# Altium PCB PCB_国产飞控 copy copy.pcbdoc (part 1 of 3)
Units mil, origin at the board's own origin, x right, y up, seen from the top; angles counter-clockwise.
Board outline 2782.5 x 2450 mil, 4 copper layers (Top Layer, Inner1, Inner2, Bottom Layer), stack 2.757 mil thick; 92 components, 104 nets, 474 pads, 149 vias.
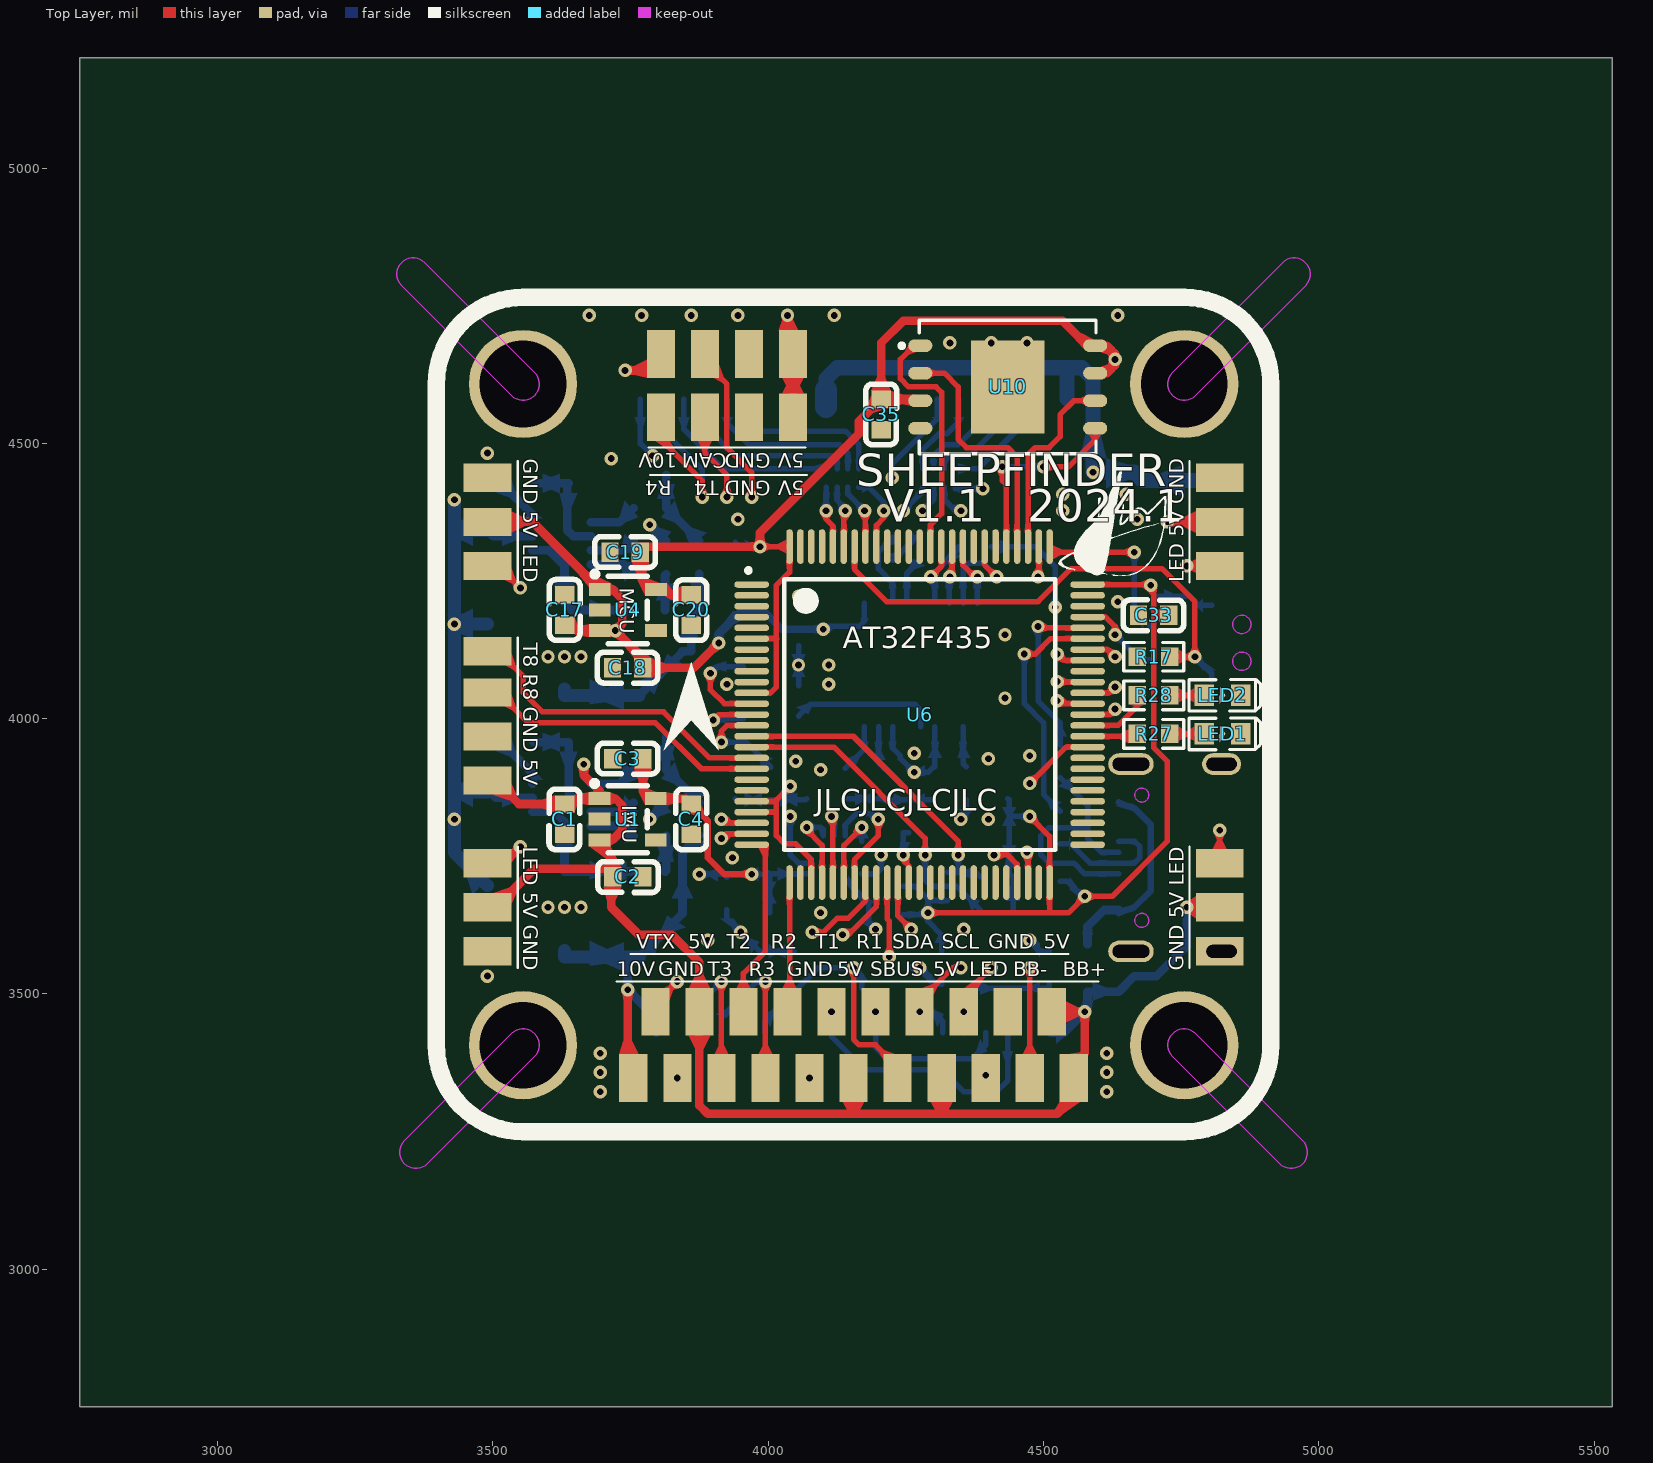
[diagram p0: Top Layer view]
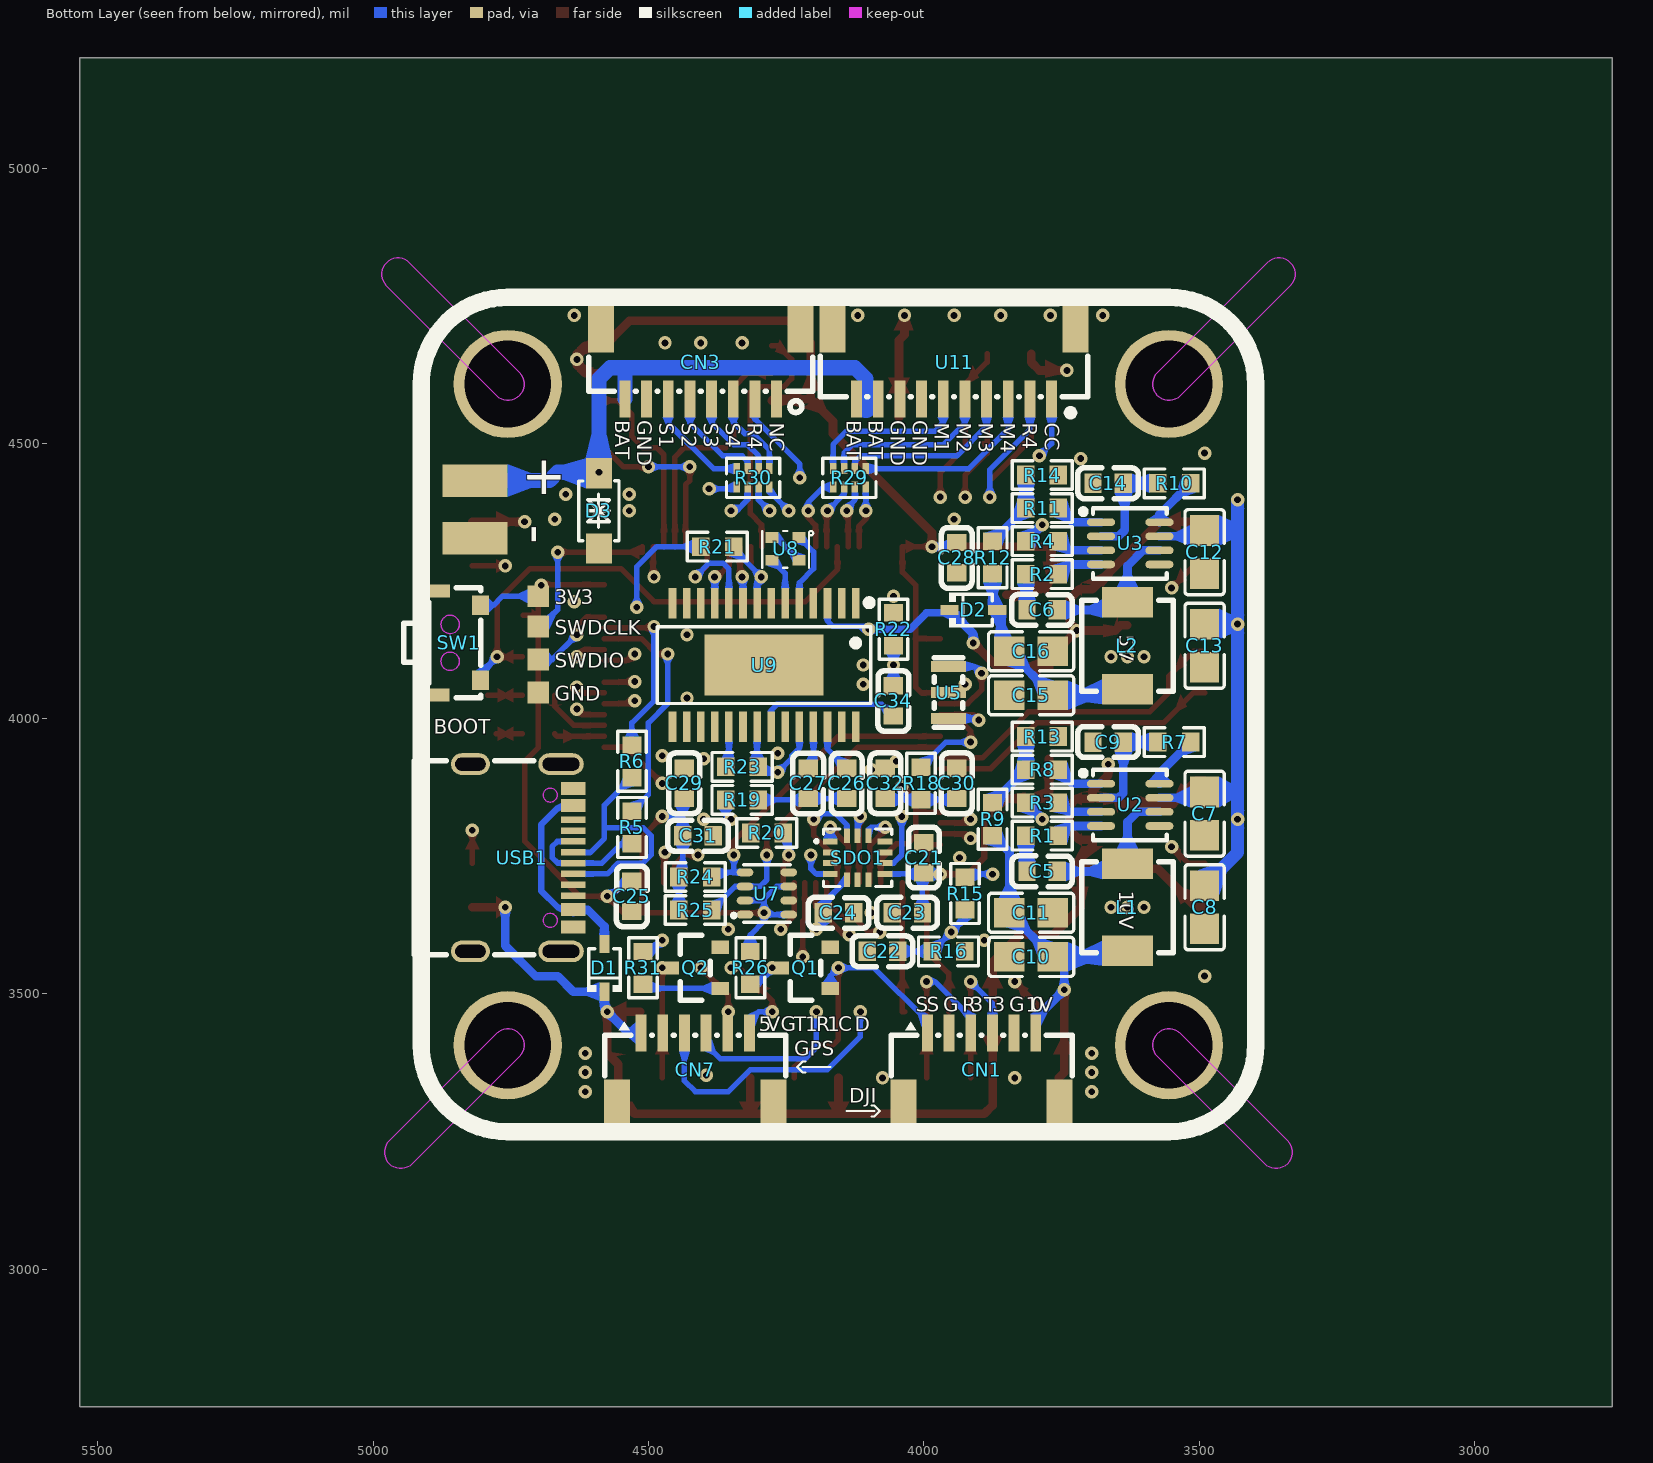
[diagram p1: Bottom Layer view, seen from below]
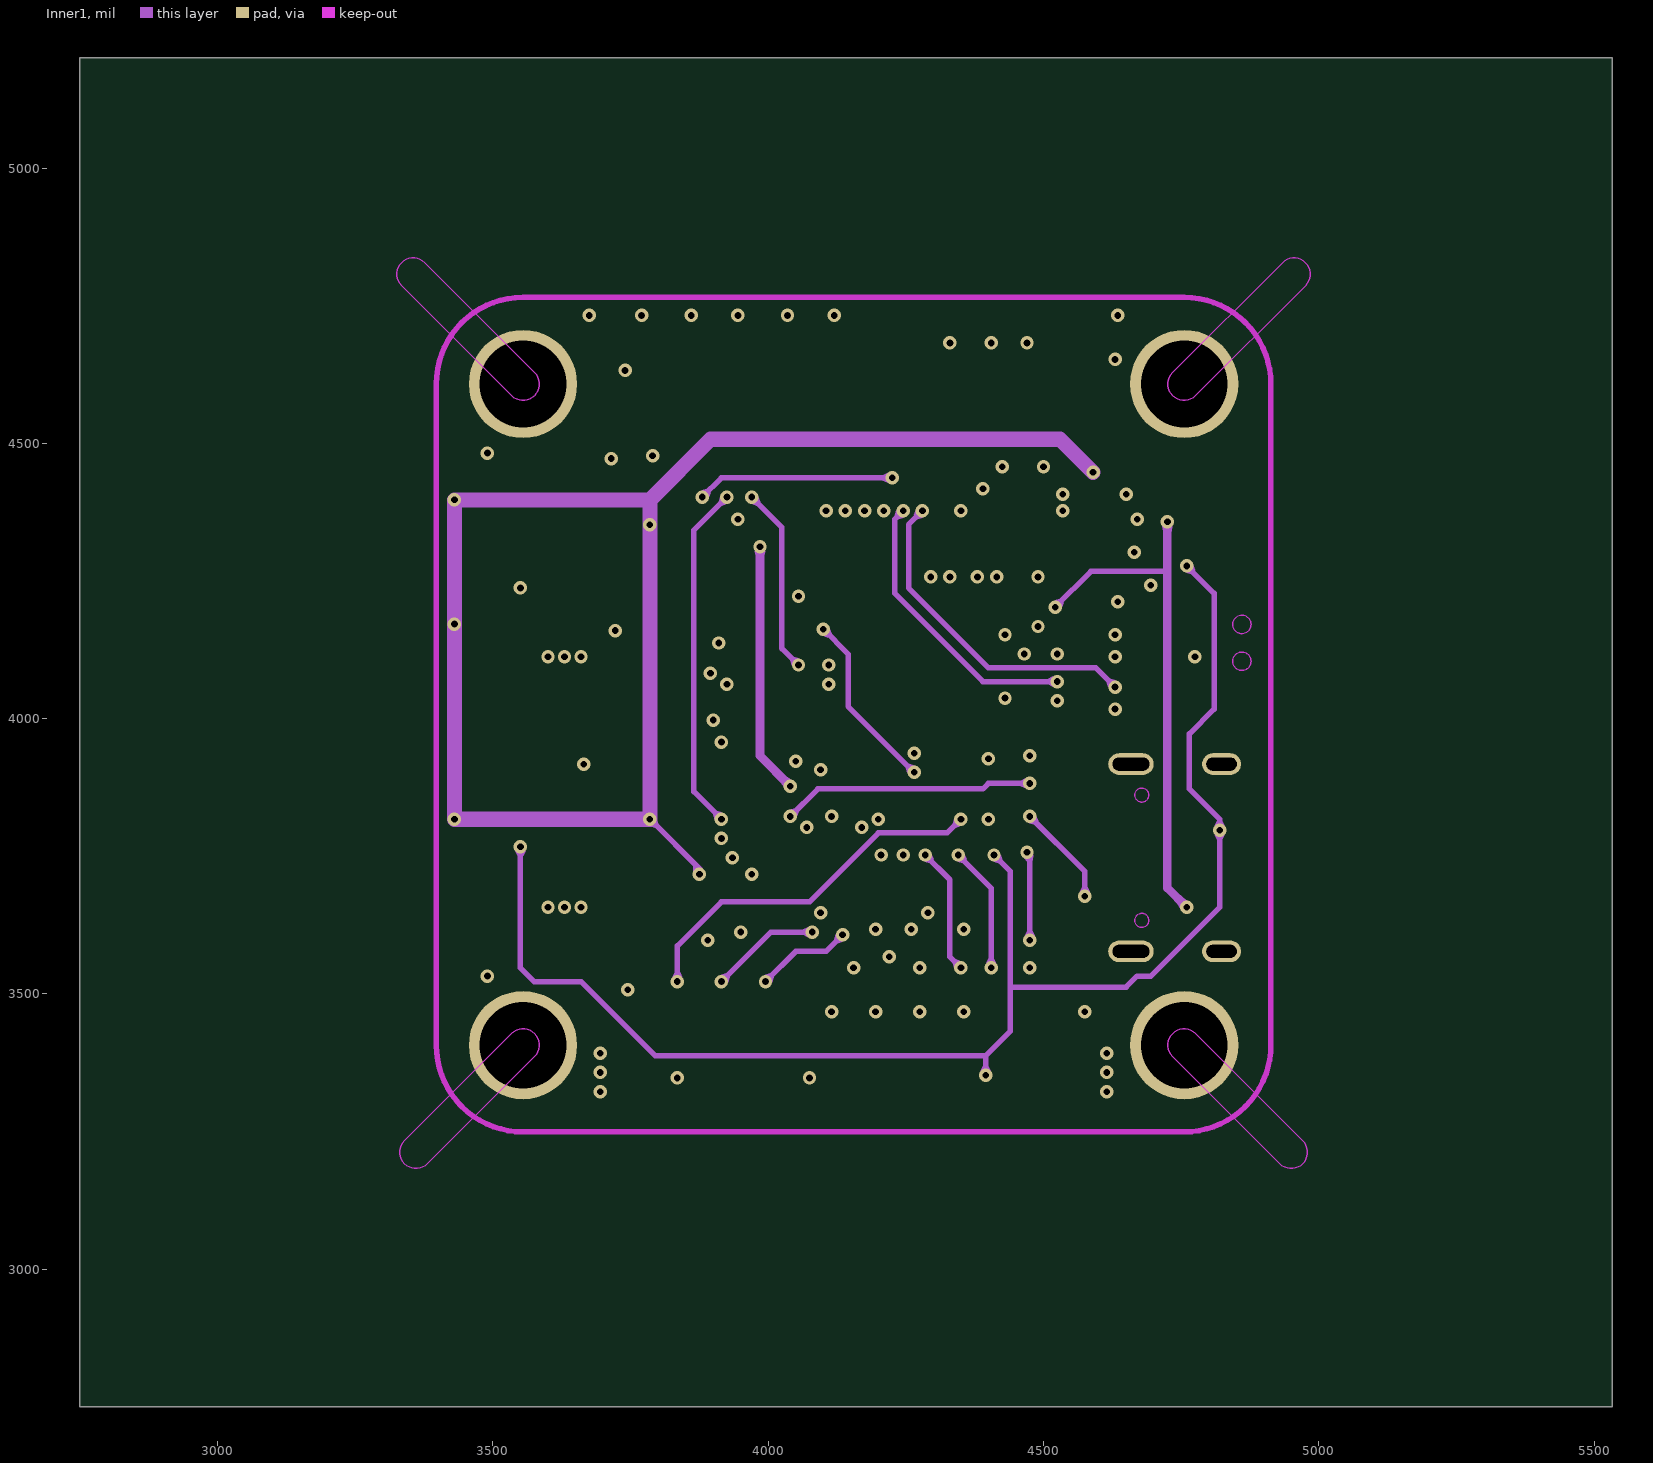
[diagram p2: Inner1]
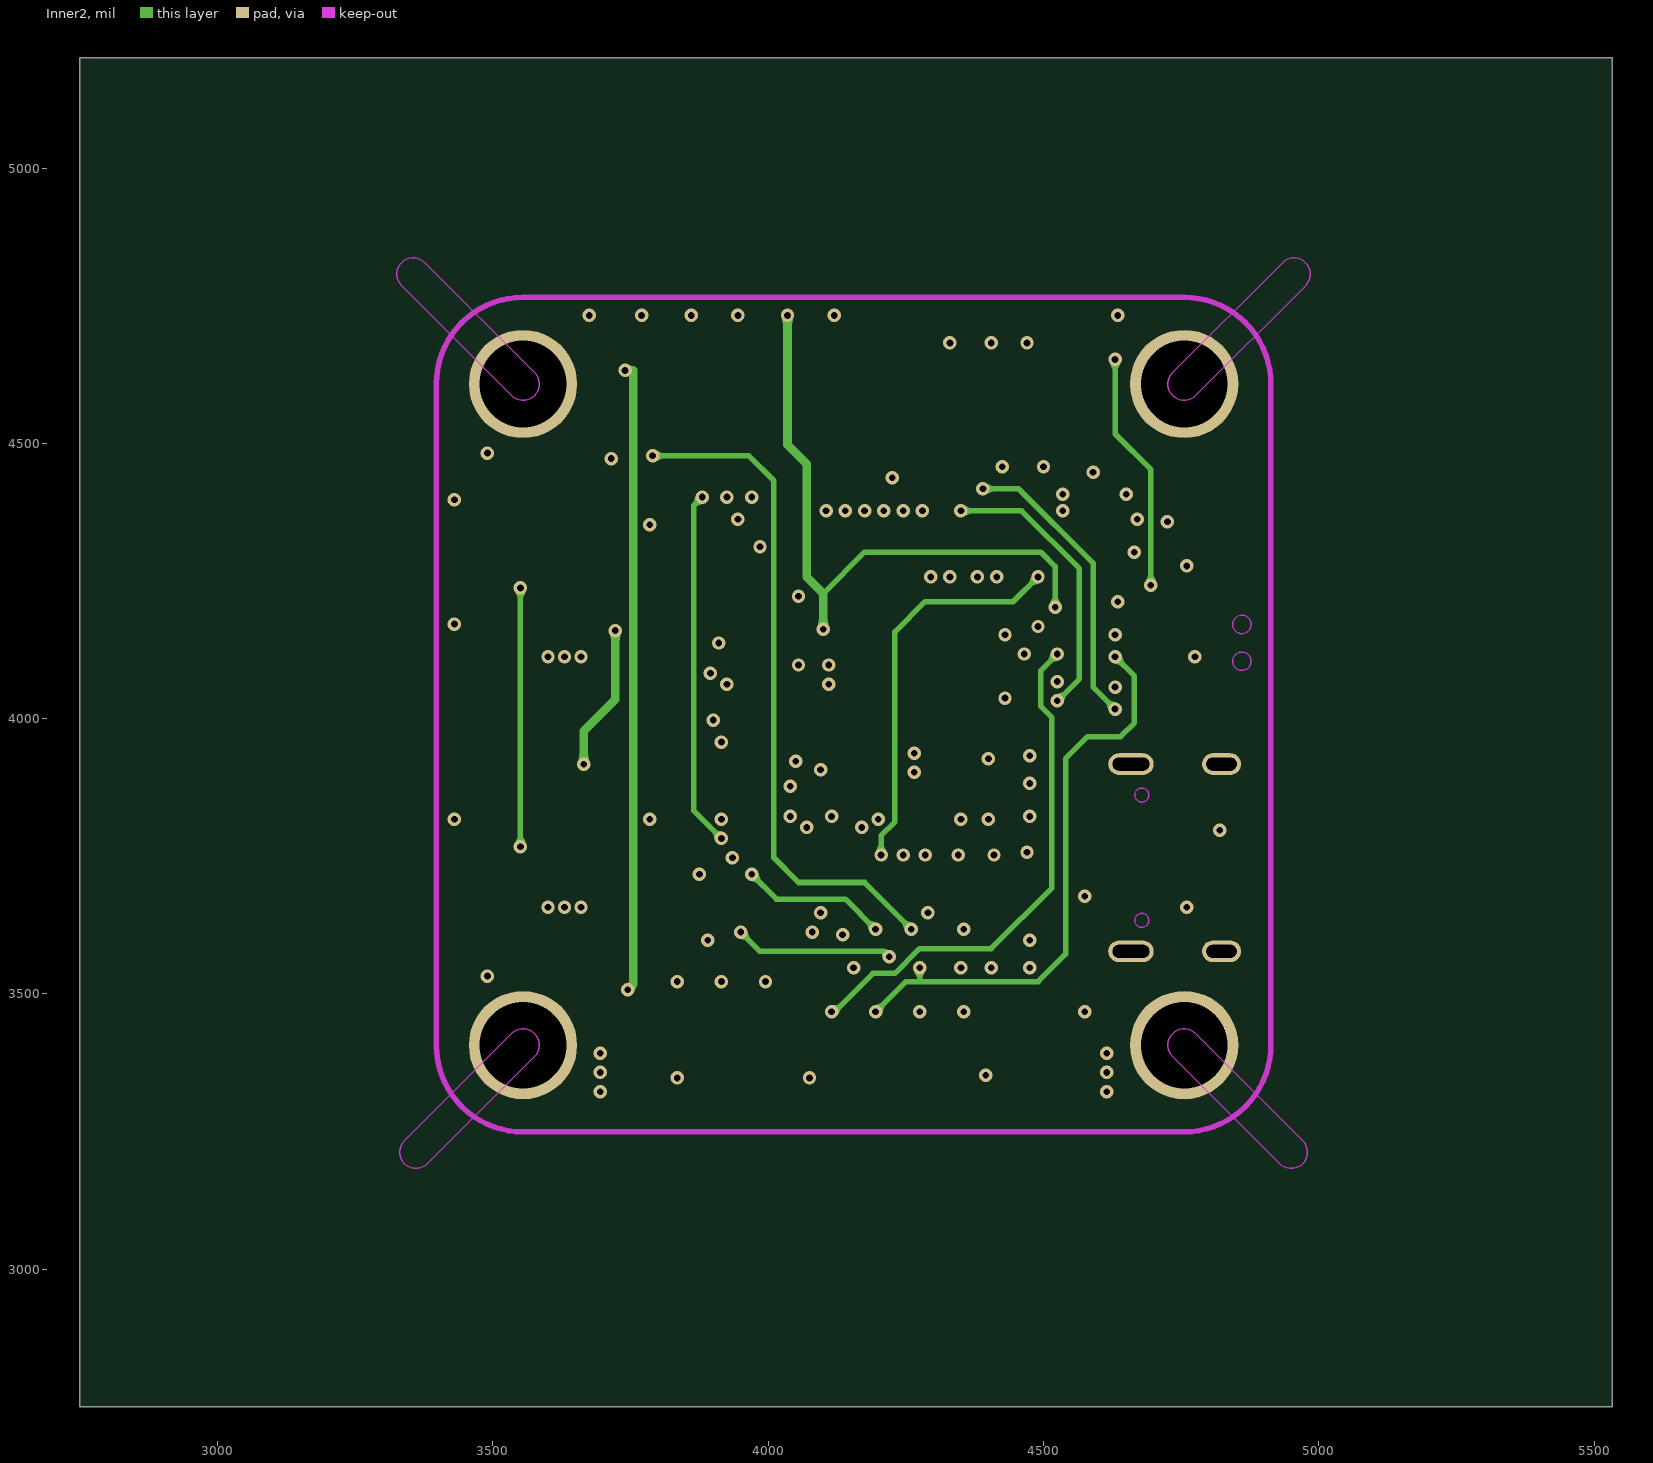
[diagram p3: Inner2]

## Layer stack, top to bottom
Top Solder Mask Layer: solder mask 0.394, Dk 3.3
Top Layer: signal copper 1.379
Inner1: signal copper (thickness not stored)
Inner2: signal copper (thickness not stored)
Bottom Layer: signal copper 1.378
Bottom Solder Mask Layer: solder mask 0.394, Dk 3.3

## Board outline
5532.5,2750 2750,2750 2750,5200 5532.5,5200

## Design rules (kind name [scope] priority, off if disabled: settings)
BoardOutlineClearance Default [All] p0: genericclearance=10 ignorepadtopadclearanceinfootprint=FALSE except(0: Arc-SplitContinuation Track-SplitContinuation SMDPad-SplitContinuation THPad-SplitContinuation Via-SplitContinuation Fill-SplitContinuation Poly-SplitContinuation Region-SplitContinuation Text-SplitContinuation)
BoardOutlineClearance otherClearance [All] p0: genericclearance=10 ignorepadtopadclearanceinfootprint=FALSE except(0: Arc-SplitContinuation Track-SplitContinuation SMDPad-SplitContinuation THPad-SplitContinuation Via-SplitContinuation Fill-SplitContinuation Poly-SplitContinuation Region-SplitContinuation Text-SplitContinuation)
Clearance Default [All] p1: gap=7 ignorepadtopadclearanceinfootprint=FALSE
Clearance otherClearance [All] p1: gap=7 ignorepadtopadclearanceinfootprint=FALSE
DiffPairsRouting differentialPair [All] p1: maxuncoupledlength=10 minlimit=5 maxlimit=Infinity mostfreqgap=6 toplayer_minwidth=5 toplayer_prefwidth=100 toplayer_maxwidth=100 bottomlayer_minwidth=5 bottomlayer_prefwidth=100 bottomlayer_maxwidth=100 midlayer1_minwidth=5 midlayer1_prefwidth=100 midlayer1_maxwidth=100 midlayer2_minwidth=5 midlayer2_prefwidth=100 midlayer2_maxwidth=100
PasteMaskExpansion pasteMaskExpansion [All] p1: expansion=0
PlaneConnect innerPlane [All] p1: planeconnectstyle=Relief reliefexpansion=20 reliefentries=4 reliefconductorwidth=10 reliefairgap=10
PolygonConnect copperRegion [All] p1: connectstyle=Relief reliefentries=4 reliefconductorwidth=10 polygonreliefangle="90 Angle" airgapwidth=10
RoutingVias Default [All] p1: viastyle="Through Hole" holewidth=12.008000000000001 minholewidth=12.008000000000001 maxholewidth=1181 width=12.008000000000001 minwidth=12.008000000000001 maxwidth=1181
SolderMaskExpansion Common [All] p1: useseparateexpansions=TRUE expansion=2 expansionbottom=2
Width Default [All] p1: maxlimit=1000 minlimit=10 preferedwidth=10

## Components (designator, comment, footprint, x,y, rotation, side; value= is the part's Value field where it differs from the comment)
C1 "100nF" C0603 3630,3817.5 r90 top
C2 "10uF" C0603 3745,3712.5 r180 top
C3 "10uF" C0603 3745,3927.5 r0 top
C4 "100nF" C0603 3860,3817.5 r90 top
C5 "100nF" C0603 3785,3722.5 r180 bottom
C6 "100nF" C0603 3785,4197.5 r180 bottom
C7 "22u" C0805 3490,3827.5 r90 bottom
C8 "22u" C0805 3490,3657.5 r90 bottom
C9 "100nF" C0603 3665,3957.5 r180 bottom
C10 "22u" C0805 3805,3567.5 r180 bottom
C11 "22u" C0805 3805,3647.5 r0 bottom
C12 "22u" C0805 3490,4302.5 r90 bottom
C13 "22u" C0805 3490,4132.5 r90 bottom
C14 "100nF" C0603 3665,4427.5 r180 bottom
C15 "22u" C0805 3805,4042.5 r180 bottom
C16 "22u" C0805 3805,4122.5 r0 bottom
C17 "100nF" C0603 3630.3,4197.5 r270 top
C18 "10uF" C0603 3744.7,4092.5 r0 top
C19 "10uF" C0603 3740.3,4302.5 r0 top
C20 "100nF" C0603 3860.3,4197.5 r90 top
C21 "10nF" C0603 4000,3747.5 r270 bottom
C22 "100nF" C0603 4075,3577.5 r180 bottom
C23 "100nF" C0603 4030,3647.5 r180 bottom
C24 "2.2uF" C0603 4155,3647.5 r0 bottom
C25 "100nF" C0603 4530,3677.5 r90 bottom
C26 "10uF" C0603 4140,3882.5 r90 bottom
C27 "10uF" C0603 4210,3882.5 r90 bottom
C28 "100nF" C0603 3940,4292.5 r90 bottom
C29 "100nF" C0603 4435,3882.5 r270 bottom
C30 "100nF" C0603 3940,3882.5 r270 bottom
C31 "100nF" C0603 4410,3787.5 r0 bottom
C32 "100nF" C0603 4070,3882.5 r270 bottom
C33 "100nF" C0603 4700,4187.5 r0 top
C34 "100nF" C0603 4055,4032.5 r90 bottom
C35 "100nF" C0603 4205,4552.5 r270 top
CN1 "SH1.0X6P" CONN-SMD_6P-P1.00_MEGASTAR_ZX-SH1.0-6PWT 3895,3362.5 r180 bottom
CN3 "SH1.0X8P" CONN-SMD_8P-P1.00_WAFER-SH1.0-8PWB 4405,4647.5 r0 bottom locked
CN7 "SH1.0X6P" CONN-SMD_6P-P1.00_MEGASTAR_ZX-SH1.0-6PWT 4415,3362.5 r180 bottom
D1 "B5817WS-MS" SOD-323_L1.7-W1.3-LS2.7-FD 4580,3547.5 r270 bottom
D2 "B5817WS-MS" SOD-323_L1.7-W1.3-LS2.7-FD 3910,4197.5 r0 bottom
D3 "SMF28CA" SOD-123_L2.7-W1.8-LS3.7-BI 4590,4377.5 r270 bottom
L1 "10uH" IND-SMD_L4.4-W4.0_PHC0420 3630,3657.5 r270 bottom
L2 "10uH" IND-SMD_L4.4-W4.0_PHC0420 3630,4132.5 r270 bottom
LED1 "LED-0603_G" LED0603_GREEN 4825,3972.5 r0 top
LED2 "LED-0603_B" LED0603_BLUE 4825,4042.5 r0 top
Q1 "S8050LT1-J3Y" SOT-23_L2.9-W1.3-P1.90-LS2.4-BR 4215,3547.5 r180 bottom
Q2 "S8050LT1-J3Y" SOT-23_L2.9-W1.3-P1.90-LS2.4-BR 4415,3547.5 r180 bottom
R1 "20R" R0603 3785,3787.5 r0 bottom
R2 "20R" R0603 3785,4262.5 r0 bottom
R3 "1M" R0603 3785,3847.5 r0 bottom
R4 "1M" R0603 3785,4322.5 r0 bottom
R5 "22R" R0603 4530,3802.5 r90 bottom
R6 "22R" R0603 4530,3922.5 r90 bottom
R7 "100k" R0603 3545,3957.5 r180 bottom
R8 "51k" R0603 3785,3907.5 r0 bottom
R9 "41.2k" R0603 3875,3817.5 r270 bottom
R10 "100k" R0603 3545,4427.5 r180 bottom
R11 "51k" R0603 3785,4382.5 r0 bottom
R12 "41.2k" R0603 3875,4292.5 r270 bottom
R13 "3.6k" R0603 3785,3967.5 r0 bottom
R14 "7.68k" R0603 3785,4442.5 r0 bottom
R15 "10k" R0603 3925,3682.5 r90 bottom
R16 "1k" R0603 3955,3577.5 r0 bottom
R17 "10k" R0603 4700,4112.5 r180 top
R18 "10k" R0603 4005,3882.5 r270 bottom
R19 "75R" R0603 4330,3852.5 r0 bottom
R20 "10k" R0603 4285,3792.5 r180 bottom
R21 "10k" R0603 4375,4312.5 r180 bottom
R22 "75R" R0603 4055,4162.5 r270 bottom
R23 "10k" R0603 4330,3912.5 r180 bottom
R24 "4K7" R0603 4415,3712.5 r0 bottom
R25 "4K7" R0603 4415,3652.5 r0 bottom
R26 "1k" R0603 4315,3547.5 r90 bottom
R27 "1k" R0603 4700,3972.5 r180 top
R28 "1k" R0603 4700,4042.5 r180 top
R29 "100*4" RES-ARRAY-SMD_0402-8P-L2.0-W1.0-BL 4135,4437.5 r0 bottom
R30 "100*4" RES-ARRAY-SMD_0402-8P-L2.0-W1.0-BL 4310,4437.5 r0 bottom
R31 "1k" R0603 4510,3547.5 r270 bottom
SDO1 "BMI270" LGA-14_L3.0-W2.5-P0.50-TL 4120,3747.5 r180 bottom
SW1 "TS-1073B-A2B2-D4" KEY-SMD_TS-1073B-A2B2-D4 4845,4137.5 r90 bottom
U1 "RT9013-33GB" SOT-23-5_L3.0-W1.7-P0.95-LS2.8-BR 3744.7,3817.5 r180 top
U2 "MP9943" QFN-8-3X3 3625,3842.5 r180 bottom
U3 "MP9943" QFN-8-3X3 3625,4317.5 r180 bottom
U4 "RT9013-33GB" SOT-23-5_L3.0-W1.7-P0.95-LS2.8-BR 3745,4197.5 r180 top
U5 "8M/3213" X3213 3955,4047.5 r90 bottom
U6 "AT32F437VMT7-LQFP100" LQFP-100_L14.0-W14.0-P0.50-LS16.0-TL 4275,4007.5 r0 top locked
U7 "BMP280" SENSOR-TH_BMP280-BL 4285,3682.5 r180 bottom
U8 "2016晶振/27M" 2016晶振 4250,4307.5 r0 bottom
U9 "AT7456E" TSSOP-28_L9.7-W4.4-P0.65-LS6.4-BL-EP5.5 4290,4097.5 r0 bottom
U10 "W25N01GVZEIG" WSON-8_L8.0-W6.10-P1.27-EP 4435,4602.5 r0 top
U11 "ZX-SH1.0-10PWT" CONN-SMD_10P-P1.00_ZX-SH1.0-10PWT 3945,4647.5 r0 bottom locked
USB1 "TYPEC-304A-16L" USB-C-SMD_XUNPU_TYPEC-304A-ACP16L 4730,3747.5 r270 bottom locked

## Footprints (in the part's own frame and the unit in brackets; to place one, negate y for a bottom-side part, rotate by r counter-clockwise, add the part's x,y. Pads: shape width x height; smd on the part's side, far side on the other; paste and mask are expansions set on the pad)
2016晶振 [mm]
  rect 0.6x0.5 smd: 1(-0.6,-0.55) 2(0.65,-0.55) 3(0.65,0.5) 4(-0.6,0.5)
  silkscreen extent -1.25,-0.85 1.1,0.85
C0603 [mm]
  rect 0.8x0.9 smd: 1(-0.7,0) 2(0.7,0)
  silkscreen extent -1.41,-0.71 1.39,0.72
C0805 [mm]
  rect 1.41x1.35 smd: 1(-1,0) 2(1,0)
  silkscreen extent -1.96,-0.9 1.96,0.9
CONN-SMD_6P-P1.00_MEGASTAR_ZX-SH1.0-6PWT [mm]
  rect 0.5x1.7 smd: 1(-2.5,1.7) 2(-1.5,1.7) 3(-0.5,1.7) 4(0.5,1.7) 5(1.5,1.7) 6(2.5,1.7)
  rect 1.2x2.5 smd: 7(3.6,-1.7) 8(-3.6,-1.7)
  silkscreen extent -4.17,-2.7 4.18,2.21
CONN-SMD_8P-P1.00_WAFER-SH1.0-8PWB [mm]
  rect 0.5x1.7 smd: 1(-3.5,1.7) 2(-2.5,1.7) 3(-1.5,1.7) 4(-0.5,1.7) 5(0.5,1.7) 6(1.5,1.7) 7(2.5,1.7) 8(3.5,1.7)
  rect 1.2x2.5 smd: 9(-4.6,-1.7) 10(4.6,-1.7)
  silkscreen extent -5.17,-2.95 5.17,2.32
CONN-SMD_10P-P1.00_ZX-SH1.0-10PWT [mm]
  rect 0.5x1.7 smd: 1(-4.5,1.7) 2(-3.5,1.7) 3(-2.5,1.7) 4(-1.5,1.7) 5(-0.5,1.7) 6(0.5,1.7) 7(1.5,1.7) 8(2.5,1.7) 9(3.5,1.7) 10(4.5,1.7)
  rect 1.2x2.5 smd: 11(5.6,-1.7) 12(-5.6,-1.7)
  silkscreen extent -6.18,-2.7 6.18,2.64
IND-SMD_L4.4-W4.0_PHC0420 [mm]
  rect 1.4x2.35 smd: 1(-2,0) 2(2,0)
  silkscreen extent -2.1,-2.1 2.1,2.1
KEY-SMD_TS-1073B-A2B2-D4 [mm]
  rect 0.9x0.8 smd: 1(-1.718,-1.013) 2(1.732,-1.013)
  rect 0.6x1.2 smd: 3(-2.407,1.013) 4(2.407,0.987)
  Board Outline Layer circle w0.003: c-0.843,0.387 r0.425
  Board Outline Layer circle w0.003: c0.857,0.387 r0.425
  Board Outline Layer region: -0.843,0.812 -1.028,0.769 -1.176,0.652 -1.258,0.481 -1.258,0.292 -1.176,0.122 -1.028,0.004 -0.843,-0.038 -0.843,-0.038 -0.659,0.004 -0.511,0.122 -0.429,0.292 -0.429,0.481 -0.511,0.652 -0.659,0.769 -0.843,0.812
  Board Outline Layer region: -0.843,0.812 -1.028,0.769 -1.176,0.652 -1.258,0.481 -1.258,0.292 -1.176,0.122 -1.028,0.004 -0.843,-0.038 -0.843,-0.038 -0.659,0.004 -0.511,0.122 -0.429,0.292 -0.429,0.481 -0.511,0.652 -0.659,0.769 -0.843,0.812
  Board Outline Layer region: 0.857,0.812 0.672,0.769 0.524,0.652 0.442,0.481 0.442,0.292 0.524,0.122 0.672,0.004 0.857,-0.038 0.857,-0.038 1.041,0.004 1.189,0.122 1.271,0.292 1.271,0.481 1.189,0.652 1.041,0.769 0.857,0.812
  Board Outline Layer region: 0.857,0.812 0.672,0.769 0.524,0.652 0.442,0.481 0.442,0.292 0.524,0.122 0.672,0.004 0.857,-0.038 0.857,-0.038 1.041,0.004 1.189,0.122 1.271,0.292 1.271,0.481 1.189,0.652 1.041,0.769 0.857,0.812
  silkscreen extent -2.53,-1.03 2.55,2.53
LED0603_BLUE [mm]
  rect 0.9x1 smd: 1(-0.85,0) 2(0.85,0)
  silkscreen extent -1.54,-0.73 1.75,0.73
LED0603_GREEN [mm]
  rect 0.9x1 smd: 1(-0.85,0) 2(0.85,0)
  silkscreen extent -1.54,-0.73 1.75,0.73
LGA-14_L3.0-W2.5-P0.50-TL [mm]
  rect 0.675x0.28 smd: 1(-1.262,0.75) 2(-1.262,0.25) 3(-1.262,-0.25) 4(-1.262,-0.75) 8(1.262,-0.75) 9(1.262,-0.25) 10(1.262,0.25) 11(1.262,0.75)
  rect 0.28x0.675 smd: 5(-0.5,-1.012) 6(0,-1.012) 7(0.5,-1.012) 12(0.5,1.012) 13(0,1.012) 14(-0.5,1.012)
  silkscreen extent -1.98,-1.33 1.58,1.33
LQFP-100_L14.0-W14.0-P0.50-LS16.0-TL [mm]
  oval 1.6x0.3 smd: 1(-7.75,6) 2(-7.75,5.5) 3(-7.75,5) 4(-7.75,4.5) 5(-7.75,4) 6(-7.75,3.5) 7(-7.75,3) 8(-7.75,2.5) 9(-7.75,2) 10(-7.75,1.5) 11(-7.75,1) 12(-7.75,0.5) 13(-7.75,0) 14(-7.75,-0.5) 15(-7.75,-1) 16(-7.75,-1.5) 17(-7.75,-2) 18(-7.75,-2.5) 19(-7.75,-3) 20(-7.75,-3.5) 21(-7.75,-4) 22(-7.75,-4.5) 23(-7.75,-5) 24(-7.75,-5.5) 25(-7.75,-6) 51(7.75,-6) 52(7.75,-5.5) 53(7.75,-5) 54(7.75,-4.5) 55(7.75,-4) 56(7.75,-3.5) 57(7.75,-3) 58(7.75,-2.5) 59(7.75,-2) 60(7.75,-1.5) 61(7.75,-1) 62(7.75,-0.5) 63(7.75,0) 64(7.75,0.5) 65(7.75,1) 66(7.75,1.5) 67(7.75,2) 68(7.75,2.5) 69(7.75,3) 70(7.75,3.5) 71(7.75,4) 72(7.75,4.5) 73(7.75,5) 74(7.75,5.5) 75(7.75,6)
  oval 0.3x1.6 smd: 26(-6,-7.75) 27(-5.5,-7.75) 28(-5,-7.75) 29(-4.5,-7.75) 30(-4,-7.75) 31(-3.5,-7.75) 32(-3,-7.75) 33(-2.5,-7.75) 34(-2,-7.75) 35(-1.5,-7.75) 36(-1,-7.75) 37(-0.5,-7.75) 38(0,-7.75) 39(0.5,-7.75) 40(1,-7.75) 41(1.5,-7.75) 42(2,-7.75) 43(2.5,-7.75) 44(3,-7.75) 45(3.5,-7.75) 46(4,-7.75) 47(4.5,-7.75) 48(5,-7.75) 49(5.5,-7.75) 50(6,-7.75) 76(6,7.75) 77(5.5,7.75) 78(5,7.75) 79(4.5,7.75) 80(4,7.75) 81(3.5,7.75) 82(3,7.75) 83(2.5,7.75) 84(2,7.75) 85(1.5,7.75) 86(1,7.75) 87(0.5,7.75) 88(0,7.75) 89(-0.5,7.75) 90(-1,7.75) 91(-1.5,7.75) 92(-2,7.75) 93(-2.5,7.75) 94(-3,7.75) 95(-3.5,7.75) 96(-4,7.75) 97(-4.5,7.75) 98(-5,7.75) 99(-5.5,7.75) 100(-6,7.75)
  silkscreen extent -8,-6.25 6.25,6.75
QFN-8-3X3 [mm]
  oval 1.3x0.35 smd: 1(-1.349,1.001) 2(-1.349,0.351) 3(-1.349,-0.3) 4(-1.349,-0.95) 5(1.346,-0.95) 6(1.346,-0.3) 7(1.346,0.351) 8(1.349,1.001)
  silkscreen extent -2.29,-1.6 1.68,1.64
R0603 [mil]
  rect 31.75x34.02 smd: 1(-29.66,0) 2(29.66,0)
  silkscreen extent -55,-26 55,26
RES-ARRAY-SMD_0402-8P-L2.0-W1.0-BL [mm]
  rect 0.3x0.505 smd: 1(-0.75,0.427) 2(-0.25,0.427) 3(0.25,0.427) 4(0.75,0.427) 5(0.75,-0.427) 6(0.25,-0.427) 7(-0.25,-0.427) 8(-0.75,-0.427)
  silkscreen extent -1.23,-0.91 1.23,0.91
SENSOR-TH_BMP280-BL [mm]
  oval 0.767x0.364 smd: 1(-1.008,-0.975) 2(-1.008,-0.325) 3(-1.008,0.325) 4(-1.008,0.975) 5(1.009,0.975) 6(1.009,0.325) 7(1.009,-0.325) 8(1.009,-0.975)
  silkscreen extent -1.61,-1.33 1.08,1.33
SOD-123_L2.7-W1.8-LS3.7-BI [mm]
  rect 1.4x1.2 smd: 1(-1.735,0) 2(1.735,0)
  silkscreen extent -1.38,-0.93 1.38,0.93
SOD-323_L1.7-W1.3-LS2.7-FD [mm]
  rect 0.845x0.455 smd: 1(-1.098,0) 2(1.098,0)
  silkscreen extent -0.88,-0.8 1.1,0.8
SOT-23-5_L3.0-W1.7-P0.95-LS2.8-BR [mm]
  rect 1x0.6 smd: 1(1.3,-0.95) 2(1.3,0) 3(1.3,0.95) 4(-1.3,0.95) 5(-1.3,-0.95)
  silkscreen extent -0.9,-1.78 1.65,1.55
SOT-23_L2.9-W1.3-P1.90-LS2.4-BR [mm]
  rect 0.8x0.6 smd: 1(1.15,-0.95) 2(1.15,0.95) 3(-1.15,0)
  silkscreen extent -0.7,-1.5 0.7,1.5
TSSOP-28_L9.7-W4.4-P0.65-LS6.4-BL-EP5.5 [mm]
  rect 0.35x1.4 smd: 1(-4.225,-2.85) 2(-3.575,-2.85) 3(-2.925,-2.85) 4(-2.275,-2.85) 5(-1.625,-2.85) 6(-0.975,-2.85) 7(-0.325,-2.85) 8(0.325,-2.85) 9(0.975,-2.85) 10(1.625,-2.85) 11(2.275,-2.85) 12(2.925,-2.85) 13(3.575,-2.85) 14(4.225,-2.85) 15(4.225,2.85) 16(3.575,2.85) 17(2.925,2.85) 18(2.275,2.85) 19(1.625,2.85) 20(0.975,2.85) 21(0.325,2.85) 22(-0.325,2.85) 23(-0.975,2.85) 24(-1.625,2.85) 25(-2.275,2.85) 26(-2.925,2.85) 27(-3.575,2.85) 28(-4.225,2.85)
  rect 5.5x2.8 smd: 29(0,0)
  silkscreen extent -5,-3.02 4.93,1.77
USB-C-SMD_XUNPU_TYPEC-304A-ACP16L [mm]
  oval 1x2.1 hole 0.6 slot 1.7 at 90 deg: 25(4.32,1.807) 28(-4.32,1.808)
  oval 1x1.8 hole 0.6 slot 1.4 at 90 deg copper offset 0,0: 26(4.32,-2.373) 27(-4.32,-2.372)
  rect 0.3x1.15 smd: A1(-3.35,2.373) A4(-2.55,2.373) A5(-1.25,2.373) A6(-0.25,2.373) A7(0.25,2.373) A8(1.25,2.373) A9(2.55,2.373) A12(3.35,2.373) B1(3.05,2.373) B4(2.25,2.373) B5(1.75,2.373) B6(0.75,2.373) B7(-0.75,2.373) B8(-1.75,2.373) B9(-2.25,2.373) B12(-3.05,2.373)
  Board Outline Layer circle w0.003: c-2.89,1.308 r0.325
  Board Outline Layer circle w0.003: c2.89,1.308 r0.325
  Board Outline Layer region: -2.89,0.983 -2.749,1.015 -2.636,1.105 -2.573,1.236 -2.573,1.38 -2.636,1.51 -2.749,1.601 -2.89,1.633 -2.89,1.633 -3.031,1.601 -3.144,1.51 -3.207,1.38 -3.207,1.236 -3.144,1.105 -3.031,1.015 -2.89,0.983
  Board Outline Layer region: -2.89,0.983 -2.749,1.015 -2.636,1.105 -2.573,1.236 -2.573,1.38 -2.636,1.51 -2.749,1.601 -2.89,1.633 -2.89,1.633 -3.031,1.601 -3.144,1.51 -3.207,1.38 -3.207,1.236 -3.144,1.105 -3.031,1.015 -2.89,0.983
  Board Outline Layer region: 2.89,0.983 3.031,1.015 3.144,1.105 3.207,1.236 3.207,1.38 3.144,1.51 3.031,1.601 2.89,1.633 2.89,1.633 2.749,1.601 2.636,1.51 2.573,1.38 2.573,1.236 2.636,1.105 2.749,1.015 2.89,0.983
  Board Outline Layer region: 2.89,0.983 3.031,1.015 3.144,1.105 3.207,1.236 3.207,1.38 3.144,1.51 3.031,1.601 2.89,1.633 2.89,1.633 2.749,1.601 2.636,1.51 2.573,1.38 2.573,1.236 2.636,1.105 2.749,1.015 2.89,0.983
  silkscreen extent -4.47,-4.97 4.47,0.54
WSON-8_L8.0-W6.10-P1.27-EP [mm]
  oval 1.115x0.581 smd: 1(-4.033,1.905) 2(-4.033,0.635) 3(-4.033,-0.635) 4(-4.033,-1.905) 5(4.033,-1.905) 6(4.033,-0.635) 7(4.033,0.635) 8(4.033,1.905)
  rect 3.4x4.3 smd: 9(0,0)
  silkscreen extent -4.99,-3.08 4.08,3.08
X3213 [mm]
  rect 0.5x1.6 smd: 1(-1.199,0) 2(0,0) 3(1.199,0)
  silkscreen extent -1.6,-0.65 1.6,0.65

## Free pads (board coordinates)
  rect 86.61x51.18 smd: 5(3490,3577.5) 5(3490,3657.5) 5(3490,3737.5) 5(3490,3887.5) 5(3490,3967.5) 5(3490,4047.5) 5(3490,4122.5) 5(3490,4277.5) 5(3490,4357.5) 5(3490,4437.5) 5(4820,3577.5) 5(4820,3657.5) 5(4820,3737.5) 5(4820,4277.5) 5(4820,4357.5) 5(4820,4437.5)
  rect 51.18x86.61 smd: 5(3755,3347.5) 5(3795,3467.5) 5(3805,4547.5) 5(3805,4662.5) 5(3835,3347.5) 5(3875,3467.5) 5(3885,4547.5) 5(3885,4662.5) 5(3915,3347.5) 5(3955,3467.5) 5(3965,4547.5) 5(3965,4662.5) 5(3995,3347.5) 5(4035,3467.5) 5(4045,4547.5) 5(4045,4662.5) 5(4075,3347.5) 5(4115,3467.5) 5(4155,3347.5) 5(4195,3467.5) 5(4235,3347.5) 5(4275,3467.5) 5(4315,3347.5) 5(4355,3467.5) 5(4395,3347.5) 5(4435,3467.5) 5(4475,3347.5) 5(4515,3467.5) 5(4555,3347.5)
  rect 39.37x39.37 smd far side: 5(4700,4047.5) 5(4700,4107.5) 5(4700,4167.5) 5(4700,4222.5)
  rect 118.11x59.05 smd far side: 5(4815,4327.5) 5(4815,4432.5)
  round 196.85 hole 157.48: 6(3554.61,4607.89) 6(3554.61,3407.11) 6(4755.39,3407.11) 6(4755.39,4607.89)

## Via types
v1: diameter 24.41, hole 12.2, Top Layer to Bottom Layer, 149 vias

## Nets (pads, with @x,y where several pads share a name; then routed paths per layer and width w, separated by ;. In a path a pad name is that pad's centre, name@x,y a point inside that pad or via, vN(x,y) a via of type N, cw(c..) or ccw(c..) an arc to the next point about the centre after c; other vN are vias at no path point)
1: pad.6@3554.61,4607.89
2: pad.6@4755.39,4607.89
3: pad.6@3554.61,3407.11
3V3-IMU: C3.2 C4.2 C21.2 C23.2 C24.2 SDO1.5 SDO1.8 U1.5 | length 911.9
  Top Layer w11.81: C4.2@3860,3845.05 3890,3815.1 3890,3747.5 3920,3717.5 v1(3970,3717.5)
  Top Layer w15.75: C3.2@3772.55,3927.5 3772.6,3868.5 3786.2,3854.9 3850.2,3854.9 C4.2@3860,3845.05
  Inner2 w10: v1(3970,3717.5) 4015,3672.5 4140,3672.5 v1(4195,3617.5)
  Bottom Layer w10: v1(3970,3717.5) 3994.1,3717.5 3994.5,3718 SDO1.8@4070.32,3717.97 ; C21.2@4000,3719.95 4002.4,3717.5 C23.2@4002.45,3647.5 ; SDO1.5@4139.69,3707.64 4182.6,3664.8 C24.2@4182.56,3647.5 4182.6,3629.9 v1(4195,3617.5)
4: pad.6@4755.39,3407.11
+5V: C1.2 C2.2 C17.2 C18.2 CN7.1 D1.2 D2.2 pad.5@3490,3657.5 pad.5@3490,3887.5 pad.5@3490,4357.5 pad.5@3875,3467.5 pad.5@4045,4547.5 pad.5@4045,4662.5 pad.5@4155,3347.5 pad.5@4315,3347.5 pad.5@4515,3467.5 pad.5@4555,3347.5 pad.5@4820,3657.5 pad.5@4820,4357.5 R21.1 R23.2 U1.1 U1.3 U4.1 U4.3 U9.3 U9.21 U9.24 | length 7359.7
  Top Layer w15.75: pad.5@3490,3657.5 3505,3657.5 3575,3727.5 3717.5,3727.5 C2.2@3717.5,3712.5 ; pad.5@3490,3887.5 3505,3887.5 3547.4,3845.1 C1.2@3630,3845.05 3642.6,3845.1 3652.4,3854.9 U1.1@3683.8,3854.9 ; pad.5@3490,4357.5 3571.2,4357.5 U4.1@3693.81,4234.9 3717.6,4234.9 3735,4217.5 3735,4172.5 3722.6,4160.1 3683.5,4160.1 3652.4,4160.1 3642.6,4169.9 C17.2@3630.3,4169.94 ; v1(3665,3917.5) 3665,3897.5 3693.5,3869 U1.1@3693.5,3854.9 3722.6,3854.9 3735,3842.5 3735,3797.5 3717.6,3780.1 U1.3@3693.51,3780.1 3693.5,3769 3717.5,3745 C2.2@3717.5,3712.5 ; U4.3@3693.81,4160.1 v1(3722.4,4160.1) 3772.3,4110.2 3772.3,4092.5 3865,4092.5 v1(3910,4137.5) ; v1(4035,4732.5) 4035,4697.5 4045,4687.5 pad.5@4045,4662.5 pad.5@4045,4547.5 ; pad.5@4155,3347.5 4155,3282.5 ; 4315,3282.5 pad.5@4315,3347.5 ; pad.5@4515,3467.5 v1(4575,3467.5) 4575,3392.5 4555,3372.5 pad.5@4555,3347.5 4555,3312.5 4525,3282.5 4155,3282.5 ; v1(4725,4357.5) pad.5@4820,4357.5 ; v1(4760,3657.5) pad.5@4820,3657.5 ; C2.2@3717.5,3712.5 3715,3710 3715,3657.5 3765,3607.5 3825,3607.5 3875,3557.5 pad.5@3875,3467.5 3875,3297.5 3890,3282.5 4155,3282.5
  Inner1 w10: v1(4100,4162.5) 4145,4117.5 4145,4022.5 v1(4265,3902.5) ; v1(4521.06,4202.57) 4586,4267.5 4725,4267.5 v1(4725,4357.5)
  Inner1 w15.75: v1(4725,4357.5) 4725,3692.5 v1(4760,3657.5)
  Inner2 w10.08: 4100,4227.5 4175,4302.5 4495,4302.5 4521.1,4276.4 v1(4521.06,4202.57)
  Inner2 w15.75: v1(3665,3917.5) 3665,3977.5 3722.4,4034.9 v1(3722.4,4160.1) ; v1(4035,4732.5) 4035,4497.5 4070,4462.5 4070,4257.5 4100,4227.5 v1(4100,4162.5)
  Bottom Layer w10: v1(4100,4162.5) 4105,4167.5 4165,4167.5 4174.8,4177.3 U9.3@4174.84,4209.7 ; U9.24@4226.02,3985.29 4226,3946.5 4240,3932.5 4240,3927.5 v1(4265,3902.5) 4290.3,3902.5 R23.2@4300.34,3912.5 4302.8,3912.5 U9.21@4302.8,3985.29 ; R21.1@4404.66,4312.5 4485,4312.5 4521.1,4276.4 v1(4521.06,4202.57)
  Bottom Layer w13.78: D2.2@3955,4192.5 3995,4192.5 4025,4162.5 v1(4100,4162.5)
  Bottom Layer w15.75: v1(3910,4137.5) 3910,4154.3 D2.2@3953.21,4197.5 ; CN7.1@4513.42,3429.43 4536.9,3429.4 v1(4575,3467.5) 4580,3472.5 D1.2@4580,3504.29 4636.8,3504.3 4665,3532.5 4705,3532.5 4760,3587.5 v1(4760,3657.5)
+10V: C10.2 C11.2 CN1.6 L1.2 pad.5@3755,3347.5 pad.5@3805,4662.5 R9.2 | length 1973.6
  Top Layer w15.75: v1(3740,4632.5) 3790,4632.5 3805,4647.5 pad.5@3805,4662.5 ; v1(3745,3507.5) 3745,3357.5 pad.5@3755,3347.5
  Inner2 w15.75: v1(3740,4632.5) 3755,4632.5 3755,3517.5 v1(3745,3507.5)
  Bottom Layer w15.75: C10.2@3740,3567.5 3745,3562.5 v1(3745,3507.5) 3796.6,3455.9 CN1.6@3796.57,3429.43 ; C10.2@3765.63,3567.5 3844.4,3646.2 C11.2@3844.37,3647.5 3844.4,3757.2 R9.2@3875,3787.84
  Bottom Layer w23.62: L1.2@3630,3578.76 3630,3567.5 C10.2@3765.63,3567.5 ; C10.2@3765.6,3562.5 C10.2@3765.63,3567.5
AT_CS: R21.2 U6.86 U9.8 | length 180
  Top Layer w10: v1(4295,4257.5) 4314.4,4276.9 U6.86@4314.37,4312.61
  Bottom Layer w10: U9.8@4302.8,4219.7 4302.8,4249.7 v1(4295,4257.5) 4345.3,4307.8 R21.2@4345.34,4312.5
AT_MISO: U6.84 U9.11 | length 117.1
  Top Layer w10: U6.84@4353.74,4312.61 4353.7,4278.8 4375,4257.5 v1(4380,4257.5)
  Bottom Layer w10: U9.11@4379.57,4209.7 4379.6,4257.5 v1(4380,4257.5)
AT_MOSI: U6.85 U9.9 | length 105.3
  Top Layer w10: v1(4330,4257.5) 4334.1,4261.6 U6.85@4334.06,4312.61
  Bottom Layer w10: U9.9@4328.39,4209.7 4328.4,4255.9 v1(4330,4257.5)
AT_SCK: U6.82 U9.10 | length 201.9
  Top Layer w10: U6.82@4393.11,4312.61 4393.1,4279.4 v1(4415,4257.5)
  Bottom Layer w10: U9.10@4353.98,4209.7 4354,4271.5 4365,4282.5 4390,4282.5 v1(4415,4257.5)
BB: pad.5@4475,3347.5 Q2.3 | length 214.8
  Top Layer w10: pad.5@4475,3347.5 v1(4475,3547.5)
  Bottom Layer w10: Q2.3@4460.25,3547.5 v1(4475,3547.5)
BEEPER: R31.1 U6.48 | length 261.4
  Top Layer w10: v1(4470,3757.5) 4471.9,3755.6 U6.48@4471.9,3702.4
  Inner1 w10: v1(4470,3757.5) 4475,3752.5 v1(4475,3597.5)
  Bottom Layer w10: v1(4475,3597.5) 4495.3,3577.2 R31.1@4510,3577.16
BOOT0: R17.1 SW1.1 U6.94 | length 934.2
  Top Layer w10: R17.1@4729.66,4112.5 v1(4775,4112.5)
  Top Layer w10.08: U6.94@4156.89,4312.61 4156.9,4270.6 4215,4212.5 4490,4212.5 4550,4272.5 4715,4272.5 4775,4212.5 v1(4775,4112.5)
  Bottom Layer w10: v1(4775,4112.5) 4805.1,4082.4 SW1.1@4805.1,4069.9
BOX_CS: U6.87 U10.1 | length 455.2
  Top Layer w10: U10.1@4276.23,4677.5 4265,4677.5 4240,4652.5 4240,4617.5 4255,4602.5 4305,4602.5 4315,4592.5 4315,4372.5 4294.7,4352.2 U6.87@4294.69,4312.61
BOX_MISO: U6.79 U10.2 | length 457.4
  Top Layer w10: U10.2@4276.23,4627.5 4320,4627.5 4345,4602.5 4345,4507.5 4360,4492.5 4435,4492.5 4452.2,4475.3 U6.79@4452.17,4312.61
BOX_MOSI: U6.80 U10.5 | length 358.2
  Top Layer w10: v1(4425,4457.5) 4425,4432.5 4432.5,4425 U6.80@4432.48,4312.61 ; v1(4500,4457.5) 4545,4457.5 4593.8,4506.3 U10.5@4593.77,4527.5
  Bottom Layer w10: v1(4425,4457.5) v1(4500,4457.5)
BOX_SCK: U6.78 U10.6 | length 352.8
  Top Layer w10: U6.78@4471.9,4312.6 4471.9,4479.4 4485,4492.5 4510,4492.5 4530,4512.5 4530,4552.5 4555,4577.5 U10.6@4593.77,4577.5
C6_1: C6.1 R2.2 | length 65.9
  Bottom Layer w15.75: C6.1@3812.55,4197.5 3812.6,4260.4 R2.2@3814.66,4262.5
C26_2: C26.2 U9.26 | length 89.6
  Bottom Layer w10: C26.2@4140,3910.05 4174.8,3944.9 U9.26@4174.84,3985.29
C27_1: C26.1 C27.1 R19.1 | length 162.7
  Bottom Layer w10: C26.1@4140,3854.95 C27.1@4210,3854.95 4210,3852.5 R19.1@4300.34,3852.5
C27_2: C27.2 U9.25 | length 79.2
  Bottom Layer w10: U9.25@4200.43,3985.29 4200.4,3919.7 C27.2@4210,3910.05
CURRENT1: U6.36 U11.1 | length 1434.8
  Top Layer w10: U6.36@4235.63,3702.39 4235.6,3641.9 v1(4260,3617.5)
  Inner2 w10: v1(3790,4477.5) 3965,4477.5 4010,4432.5 4010,3747.5 4055,3702.5 4175,3702.5 v1(4260,3617.5)
  Bottom Layer w10: U11.1@3767.82,4580.57 3767.8,4499.7 v1(3790,4477.5)
D+: R6.2 U6.71 | length 323
  Top Layer w10: v1(4490,4167.5) 4492.5,4165 U6.71@4580.11,4164.98
  Bottom Layer w10: v1(4490,4167.5) 4490,4032.5 4530,3992.5 R6.2@4530,3952.16
D-: R5.2 U6.70 | length 438.8
  Top Layer w10: v1(4465,4117.5) 4485,4117.5 4512.8,4145.3 U6.70@4580.11,4145.3
  Bottom Layer w10: v1(4465,4117.5) 4465,4027.5 4500,3992.5 4500,3862.2 R5.2@4530,3832.16
DN: R5.1 USB1.A7 USB1.B7 | length 225.7
  Bottom Layer w10: R5.1@4530,3772.84 4549.7,3772.8 4584.8,3737.7 USB1.A7@4636.59,3737.66 4664.8,3737.7 4675,3747.9 4675,3767.5 4665.5,3777 USB1.B7@4636.59,3777.03
DP: R6.1 USB1.A6 USB1.B6 | length 480
  Bottom Layer w10: R6.1@4530,3892.84 4580,3842.8 4580,3782.5 4605.2,3757.3 USB1.A6@4636.59,3757.34 ; 4580,3802.1 4509.6,3802.1 4495,3787.5 4495,3752.5 4510,3737.5 4555,3737.5 4574.5,3718 USB1.B6@4636.59,3717.97
GND: C1.1 C2.1 C3.1 C4.1 C7.1 C8.1 C9.1 C10.1 C11.1 C12.1 C13.1 C14.1 C15.1 C16.1 C17.1 C18.1 C19.1 C20.1 C21.1 C22.1 C23.1 C24.1 C25.1 C28.1 C29.1 C30.1 C31.1 C32.1 C33.1 C35.2 CN1.2 CN1.5 CN1.7 CN1.8 CN3.7 CN3.9 CN3.10 CN7.2 CN7.7 CN7.8 D3.2 LED1.2 LED2.2 pad.5@3490,3577.5 pad.5@3490,3967.5 pad.5@3490,4437.5 pad.5@3835,3347.5 pad.5@3965,4547.5 pad.5@3965,4662.5 pad.5@4075,3347.5 pad.5@4435,3467.5 pad.5@4700,4047.5 pad.5@4815,4327.5 pad.5@4820,3577.5 pad.5@4820,4437.5 Q1.2 Q2.2 R13.1 R14.1 R16.1 R17.2 R20.1 R22.1 SDO1.6 SDO1.7 U1.2 U2.5 U3.5 U4.2 U5.2 U6.10 U6.20 U6.27 U6.74 U6.99 U7.1 U7.5 U7.7 U8.2 U8.4 U9.4 U9.20 U9.23 U10.4 U10.9 U11.7 U11.8 U11.11 U11.12 USB1.25 USB1.26 USB1.27 USB1.28 USB1.A1 USB1.A12 USB1.B1 USB1.B12 | length 66.4
  Bottom Layer w10: U8.4@4226.38,4287.81 4267.7,4329.2 U8.2@4275.6,4329.2
  other v1: 3695,3322.5 4615,3322.5 3835,3347.5 4075,3347.5 3695,3357.5 4615,3357.5 3695,3392.5 4615,3392.5 3490,3532.5 3890,3597.5 4355,3617.5 4095,3647.5 3600,3657.5 3630,3657.5 3660,3657.5 3935,3747.5 4400,3817.5 4095,3907.5 4050,3922.5 4400,3927.5 4475,3932.5 4265,3937.5 4430,4037.5 3925,4062.5 4110,4062.5 4110,4097.5 3600,4112.5 3630,4112.5 3660,4112.5 4430,4152.5 4635,4212.5 4055,4222.5 3945,4362.5 4670,4362.5 4535,4377.5 4535,4407.5 4650,4407.5 3715,4472.5 3490,4482.5 4330,4682.5 4405,4682.5 4470,4682.5 3675,4732.5 3770,4732.5 3860,4732.5 3945,4732.5 4120,4732.5 4635,4732.5
GYRO_CS1: SDO1.12 U6.29 | length 153.9
  Top Layer w10: v1(4070,3802.5) 4070,3797.5 4097.8,3769.7 U6.29@4097.83,3702.39
  Bottom Layer w10: v1(4070,3802.5) 4095,3802.5 4100.3,3797.2 SDO1.12@4100.31,3787.36
GYRO_EXTI1: SDO1.4 U6.77 | length 837.6
  Top Layer w10: v1(4490,4257.5) 4491.5,4257.5 U6.77@4491.54,4312.61
  Inner2 w10: v1(4205,3752.5) 4205,3787.5 4230,3812.5 4230,4157.5 4285,4212.5 4445,4212.5 v1(4490,4257.5)
  Bottom Layer w10: SDO1.4@4169.69,3717.97 4195.5,3718 4205,3727.5 v1(4205,3752.5)
GYRO_EXTI2: SDO1.9 U6.60 | length 698.7
  Top Layer w10: v1(4475,3882.5) 4540.9,3948.4 U6.60@4580.11,3948.44
  Inner1 w10: v1(4040,3822.5) 4090,3872.5 4390,3872.5 4400,3882.5 v1(4475,3882.5)
  Bottom Layer w10: v1(4040,3822.5) 4040,3752.5 4054.8,3737.7 SDO1.9@4070.32,3737.66
GYRO_MISO: SDO1.1 U6.31 | length 139.3
  Top Layer w10: U6.31@4137.2,3702.39 4137.2,3769.7 v1(4170,3802.5)
  Bottom Layer w10: SDO1.1@4169.69,3777.03 4170,3777.3 v1(4170,3802.5)
GYRO_MOSI: SDO1.14 U6.32 | length 225.6
  Top Layer w10: U6.32@4156.89,3702.39 4156.9,3744.4 4200,3787.5 v1(4200,3817.5)
  Bottom Layer w10: SDO1.14@4139.69,3787.36 4139.7,3807.2 4160,3827.5 4185,3827.5 4195,3817.5 v1(4200,3817.5)
GYRO_SCK: SDO1.13 U6.30 | length 161.2
  Top Layer w10: v1(4115,3822.5) 4117.5,3820 U6.30@4117.52,3702.39
  Bottom Layer w10: v1(4115,3822.5) 4120,3822.5 SDO1.13@4120,3787.36
HEXT_IN: U5.3 U6.12 | length 180.4
  Top Layer w10: v1(3895,4082.5) 3895,4052.5 3920.3,4027.2 U6.12@3969.89,4027.18
  Bottom Layer w10: v1(3895,4082.5) 3907.2,4094.7 U5.3@3955,4094.7
HEXT_OUT: U5.1 U6.13 | length 131.8
  Top Layer w10: v1(3900,3997.5) 3910,4007.5 U6.13@3969.89,4007.5
  Bottom Layer w10: v1(3900,3997.5) 3900,4000.3 U5.1@3955,4000.3
I2C_SCL: CN7.5 pad.5@4355,3467.5 R24.1 U6.15 U7.4 | length 945.5
  Top Layer w10: U6.15@3969.89,3968.13 4154.4,3968.1 4345,3777.5 v1(4345,3752.5) ; v1(4355,3467.5) 4355,3497.5 v1(4405,3547.5)
  Inner1 w10: v1(4345,3752.5) 4405,3692.5 v1(4405,3547.5)
  Bottom Layer w10: U7.4@4324.7,3720.89 4377,3720.9 R24.1@4385.34,3712.5 ; v1(4345,3752.5) 4345,3725.9 4350,3720.9 ; v1(4355,3467.5) CN7.5@4355.94,3429.43
I2C_SDA: CN7.6 pad.5@4275,3467.5 R25.1 U6.16 U7.3 | length 1003.7
  Top Layer w10: U6.16@3969.89,3948.44 4119.1,3948.4 4285,3782.5 v1(4285,3752.5) ; v1(4275,3467.5) 4275,3487.5 4335,3547.5 v1(4350,3547.5)
  Inner1 w10: v1(4285,3752.5) 4330,3707.5 4330,3567.5 v1(4350,3547.5)
  Bottom Layer w10: v1(4275,3467.5) 4300,3467.5 4316.6,3450.9 CN7.6@4316.57,3429.43 ; v1(4285,3752.5) 4285,3707.5 4297.2,3695.3 U7.3@4324.7,3695.3 4342.5,3695.3 R25.1@4385.34,3652.5
L1_1: C5.2 L1.1 U2.6 | length 282.9
  Bottom Layer w15.75: U2.6@3572,3830.7 3611.8,3830.7 3630,3812.5 L1.1@3630,3736.24 3630,3722.5 C5.2@3757.45,3722.5
LED: pad.5@3490,3737.5 pad.5@3490,4277.5 pad.5@4395,3347.5 pad.5@4820,3737.5 pad.5@4820,4277.5 U6.47 | length 3545.8
  Top Layer w10: pad.5@3490,3737.5 3520,3737.5 v1(3550,3767.5) ; pad.5@3490,4277.5 3510,4277.5 v1(3550,4237.5) ; pad.5@4395,3347.5 v1(4395,3352.5) ; v1(4410,3752.5) 4435,3752.5 4452.2,3735.3 U6.47@4452.17,3702.39 ; v1(4760,4277.5) pad.5@4820,4277.5 ; pad.5@4820,3737.5 v1(4820,3797.5)
  Inner1 w10: v1(3550,3767.5) 3550,3547.5 3575,3522.5 3660,3522.5 3795,3387.5 4395,3387.5 ; v1(4410,3752.5) 4440,3722.5 4440,3432.5 4395,3387.5 ; 4440,3512.5 4650,3512.5 4670,3532.5 4695,3532.5 4820,3657.5 v1(4820,3797.5) 4820,3817.5 4765,3872.5 4765,3972.5 4810,4017.5 4810,4227.5 v1(4760,4277.5) ; 4395,3387.5 v1(4395,3352.5) 4395,3387.5
  Inner2 w10: v1(3550,3767.5) v1(3550,4237.5)
LED1: R27.2 U6.61 | length 92
  Top Layer w10: U6.61@4580.11,3968.13 4665.9,3968.1 R27.2@4670.34,3972.5
LED2: R28.2 U6.62 | length 124.4
  Top Layer w10: U6.62@4580.11,3987.81 4635.3,3987.8 4670.3,4022.8 R28.2@4670.34,4042.5
MOTOR1: R29.4 U6.92 | length 142.7
  Top Layer w10: U6.92@4196.26,4312.61 4196.3,4351.2 4210,4365 v1(4210,4377.5)
  Bottom Layer w10: R29.4@4164.53,4420.67 4181.8,4420.7 4210,4392.5 v1(4210,4377.5)
MOTOR2: R29.3 U6.93 | length 122.2
  Top Layer w10: v1(4175,4377.5) 4176.6,4377.5 U6.93@4176.57,4312.61
  Bottom Layer w10: R29.3@4144.84,4420.67 4144.8,4407.7 v1(4175,4377.5)
MOTOR3: R29.2 U6.95 | length 117
  Top Layer w10: U6.95@4137.2,4312.61 4137.2,4377.5 v1(4140,4377.5)
  Bottom Layer w10: R29.2@4125.16,4420.67 4125.2,4397.3 4140,4382.5 v1(4140,4377.5)
MOTOR4: R29.1 U6.96 | length 113.5
  Top Layer w10: v1(4105,4377.5) 4105,4362.5 4117.5,4350 U6.96@4117.52,4312.61
  Bottom Layer w10: v1(4105,4377.5) 4105,4420.2 R29.1@4105.47,4420.67
OSD_IN_CAM: C34.2 pad.5@3885,4662.5 R22.2 | length 708.1
  Top Layer w10: pad.5@3885,4662.5 3885,4647.5 3925,4607.5 3925,4492.5 3970,4447.5 v1(3970,4402.5)
  Inner1 w10: v1(3970,4402.5) 4025,4347.5 4025,4127.5 v1(4055,4097.5)
  Bottom Layer w10: C34.2@4055,4060.05 R22.2@4055,4132.84
OSD_OUT_VTX: pad.5@3795,3467.5 R19.2 | length 785.9
  Top Layer w10: pad.5@3795,3467.5 3795,3482.5 v1(3835,3522.5)
  Inner1 w10: v1(3835,3522.5) 3835,3587.5 3915,3667.5 4075,3667.5 4200,3792.5 4325,3792.5 v1(4350,3817.5)
  Bottom Layer w10: v1(4350,3817.5) 4359.7,3827.2 R19.2@4359.66,3852.5
Q2_1: Q2.1 R31.2 | length 147.9
  Bottom Layer w10: Q2.1@4369.8,3510.1 4510,3510.1 R31.2@4510,3517.84
R1_1: R1.1 U2.4 | length 84.5
  Bottom Layer w15.75: U2.4@3678.1,3805.1 3737.7,3805.1 R1.1@3755.34,3787.5
R1_2: C5.1 R1.2 | length 65.9
  Bottom Layer w15.75: C5.1@3812.55,3722.5 3814.7,3724.6 R1.2@3814.66,3787.5
R3_1: R3.1 U2.3 | length 84.2
  Bottom Layer w15.75: U2.3@3678.1,3830.7 3738.5,3830.7 R3.1@3755.34,3847.5
R7_1: C9.2 R7.1 U2.2 | length 199.4
  Bottom Layer w15.75: R7.1@3574.66,3957.5 C9.2@3637.45,3957.5 3637.4,3865.1 3646.2,3856.3 U2.2@3678.1,3856.3
R7_2: R7.2 U2.8 | length 99
  Bottom Layer w15.75: R7.2@3515.34,3957.5 3571.9,3900.9 U2.8@3571.9,3881.9
R8_1: R8.1 U2.1 | length 87.8
  Bottom Layer w15.75: U2.1@3678.1,3881.9 3729.7,3881.9 R8.1@3755.34,3907.5
R11_2: R11.2 R12.1 R14.2 | length 145.3
  Bottom Layer w15.75: R14.2@3814.66,4442.5 R11.2@3814.66,4382.5 R12.1@3875,4322.16
R12_2: C15.2 C16.2 D2.1 L2.2 R12.2 | length 426.5
  Bottom Layer w15.75: C15.2@3765.63,4042.5 3844.4,4121.2 C16.2@3844.37,4122.5 3860,4122.5 3860,4190.7 D2.1@3866.79,4197.5 3875,4197.5 R12.2@3875,4262.84
  Bottom Layer w23.62: L2.2@3630,4053.76 3630,4042.5 C15.2@3765.63,4042.5
R13_2: R8.2 R9.1 R13.2 | length 145.3
  Bottom Layer w15.75: R13.2@3814.66,3967.5 R8.2@3814.66,3907.5 R9.1@3875,3847.16
R27_1: LED1.1 R27.1 | length 46.8
  Top Layer w10: R27.1@4729.66,3972.5 LED1.1@4776.5,3972.5
R28_1: LED2.1 R28.1 | length 61.8
  Top Layer w10: R28.1@4729.66,4042.5 LED2.1@4791.53,4042.5
R29_5: R29.5 U11.6 | length 302.8
  Bottom Layer w10: U11.6@3964.68,4580.57 3964.7,4537.8 3980,4522.5 4140,4522.5 4164.5,4498 R29.5@4164.53,4454.33
R29_6: R29.6 U11.5 | length 313.9
  Bottom Layer w10: U11.5@3925.31,4580.57 3925.3,4537.2 3965,4497.5 4130,4497.5 4144.8,4482.7 R29.6@4144.84,4454.33
R29_7: R29.7 U11.4 | length 327.9
  Bottom Layer w10: U11.4@3885.94,4580.57 3885.9,4531.6 3940,4477.5 4115,4477.5 4125.2,4467.3 R29.7@4125.16,4454.33
R29_8: R29.8 U11.3 | length 343.3
  Bottom Layer w10: U11.3@3846.56,4580.57 3846.6,4525.9 3918.2,4454.3 R29.8@4105.47,4454.33
R30_5: CN3.6 R30.5 | length 202.7
  Bottom Layer w10: R30.5@4339.53,4454.33 4381.8,4454.3 4464.1,4536.6 CN3.6@4464.1,4580.6
R30_6: CN3.5 R30.6 | length 190.3
  Bottom Layer w10: R30.6@4319.84,4454.33 4319.8,4467.3 4330,4477.5 4365,4477.5 4424.7,4537.2 CN3.5@4424.68,4580.57
R30_7: CN3.4 R30.7 | length 176.2
  Bottom Layer w10: R30.7@4300.16,4454.33 4300.2,4477.7 4320,4497.5 4345,4497.5 4385.3,4537.8 CN3.4@4385.31,4580.57
R30_8: CN3.3 R30.8 | length 162.2
  Bottom Layer w10: R30.8@4280.47,4454.33 4280.5,4488 4310,4517.5 4325,4517.5 4345.9,4538.4 CN3.3@4345.94,4580.57
S$147824: 
S$244950: 
S$244954: 
SBUS: CN1.1 pad.5@4235,3347.5 Q1.1 | length 517.4
  Top Layer w10: v1(4155,3547.5) 4155,3417.5 4165,3407.5 4195,3407.5 4235,3367.5 pad.5@4235,3347.5
  Bottom Layer w10: CN1.1@3993.42,3429.43 3993.4,3450.9 4090,3547.5 v1(4155,3547.5) 4169.8,3532.7 Q1.1@4169.8,3510.1
SERVO1: R30.4 U6.63 | length 645.2
  Top Layer w10: U6.63@4580.11,4007.5 4620,4007.5 v1(4630,4017.5)
  Inner2 w10: v1(4390,4417.5) 4455,4417.5 4590,4282.5 4590,4057.5 v1(4630,4017.5)
  Bottom Layer w10: R30.4@4339.53,4420.67 4339.5,4417.5 v1(4390,4417.5)
SERVO2: R30.3 U6.64 | length 633.9
  Top Layer w10: v1(4525,4032.5) 4530.3,4027.2 U6.64@4580.11,4027.18
  Inner2 w10: v1(4350,4377.5) 4460,4377.5 4565,4272.5 4565,4072.5 v1(4525,4032.5)
  Bottom Layer w10: R30.3@4319.84,4420.67 4319.8,4397.7 4340,4377.5 v1(4350,4377.5)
